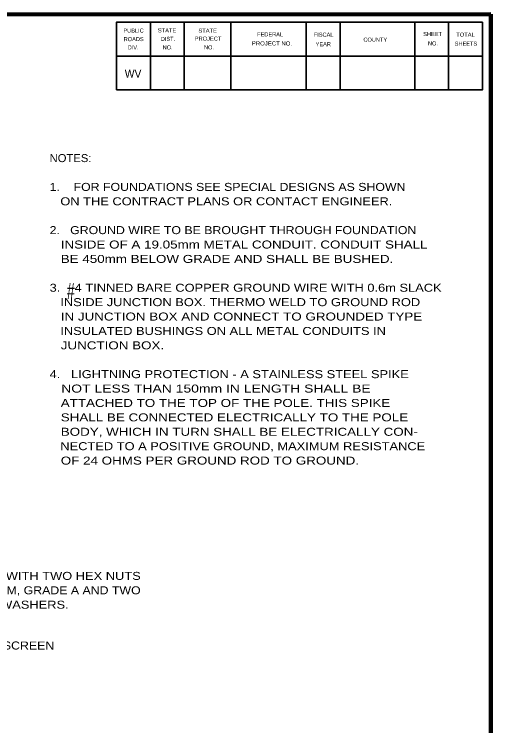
# Model space of a CAD drawing. Extents: x -24 to 689, y -7 to 446.
# Drawn here: x 534.7 to 683.4, y 218.4 to 440.6 of the extents above; entities that cross this region are included whole.
import ezdxf
from ezdxf.enums import TextEntityAlignment as Align

# ---------------------------------------------------------------- set-up
doc = ezdxf.new("R2010")
doc.units = 0
doc.layers.add('1', color=7, linetype='Continuous', lineweight=35)
doc.layers.add('61', color=7, linetype='Continuous', lineweight=35)

msp = doc.modelspace()

# ---------------------------------------------------------------- linework, layer by layer
at = {"layer": '1', "lineweight": 158}
msp.add_line((683.413, 2.23), (683.413, 440.647), dxfattribs=at)
at = {"layer": '1', "lineweight": 13}
msp.add_line((683.413, 2.23), (683.413, 440.647), dxfattribs=at)
at = {"layer": '1', "lineweight": 158}
msp.add_lwpolyline([(683.413, 440.647), (23.663, 440.564), (23.747, 2.23)], dxfattribs=at)
at = {"layer": '61'}
for p, q in [((577.163, 438.147), (577.163, 416.98)), ((587.747, 438.147), (587.747, 416.98)), ((602.247, 438.147), (602.247, 416.98)), ((625.83, 438.147), (625.83, 416.98)), ((636.413, 438.147), (636.413, 416.98)), ((659.663, 438.147), (659.663, 416.98)), ((670.247, 438.147), (670.247, 416.98)), ((680.83, 427.564), (566.58, 427.564))]:
    msp.add_line(p, q, dxfattribs=at)
for points in [[(680.83, 438.147), (566.58, 438.147), (566.58, 416.98)], [(680.83, 438.147), (680.83, 416.98), (566.58, 416.98)]]:
    msp.add_lwpolyline(points, dxfattribs=at)

# ---------------------------------------------------------------- texts
at = {"layer": '1'}
for s, height, width, p in [('WV', 2.54, 0.95, (569.163, 420.814)), ('NOTES:', 2.5, 1.05, (545.702, 394.452)), ('1.    FOR FOUNDATIONS SEE SPECIAL DESIGNS AS SHOWN', 2.5, 1.15, (545.702, 385.452)), ('   ON THE CONTRACT PLANS OR CONTACT ENGINEER.', 2.5, 1.2, (545.702, 380.952)), ('2.   GROUND WIRE TO BE BROUGHT THROUGH FOUNDATION', 2.5, 1.15, (545.702, 371.952)), ('   INSIDE OF A 19.05mm METAL CONDUIT. CONDUIT SHALL', 2.5, 1.25, (545.702, 367.452)), ('   BE 450mm BELOW GRADE AND SHALL BE BUSHED.', 2.5, 1.25, (545.702, 362.952)), ('3.    4 TINNED BARE COPPER GROUND WIRE WITH 0.6m SLACK', 2.5, 1.2, (545.702, 353.952)), ('   INSIDE JUNCTION BOX. THERMO WELD TO GROUND ROD', 2.5, 1.2, (545.702, 349.452)), ('   IN JUNCTION BOX AND CONNECT TO GROUNDED TYPE', 2.5, 1.25, (545.702, 344.952)), ('   INSULATED BUSHINGS ON ALL METAL CONDUITS IN', 2.5, 1.2, (545.702, 340.452)), ('   JUNCTION BOX.', 2.5, 1.25, (545.702, 335.952)), ('4.   LIGHTNING PROTECTION - A STAINLESS STEEL SPIKE', 2.5, 1.2, (545.702, 326.952)), ('   NOT LESS THAN 150mm IN LENGTH SHALL BE', 2.5, 1.3, (545.702, 322.452)), ('   ATTACHED TO THE TOP OF THE POLE. THIS SPIKE', 2.5, 1.25, (545.702, 317.952)), ('   SHALL BE CONNECTED ELECTRICALLY TO THE POLE', 2.5, 1.25, (545.702, 313.452)), ('   BODY, WHICH IN TURN SHALL BE ELECTRICALLY CON-', 2.5, 1.25, (545.702, 308.952)), ('   NECTED TO A POSITIVE GROUND, MAXIMUM RESISTANCE', 2.5, 1.2, (545.702, 304.452)), ('   OF 24 OHMS PER GROUND ROD TO GROUND.', 2.5, 1.25, (545.702, 299.952)), ('EACH BOLT PROVIDED WITH TWO HEX NUTS', 2.5, 1.2, (486.114, 263.93)), ('MEETING AASHTO M291/M, GRADE A AND TWO', 2.5, 1.15, (486.114, 259.43)), ('AASHTO M243/M FLAT WASHERS.', 2.5, 1.2, (486.114, 254.93))]:
    msp.add_text(s, height=height, dxfattribs=dict(at, width=width)).set_placement(p)
for s, height, width, p in [('#', 5, 0.65, (552.302, 351.66)), ('INSTALL VARMINT SCREEN', 2.5, 1.15, (521.609, 242.181))]:
    msp.add_text(s, height=height, dxfattribs=dict(at, width=width)).set_placement(p, align=Align.CENTER)
at = {"layer": '61'}
for s, height, rotation, p in [('PUBLIC', 1.271, 0.033, (568.747, 434.897)), ('ROADS', 1.27, 0.124, (568.83, 432.23)), ('DIST.', 1.27, 0.056, (580.413, 432.314)), ('FEDERAL', 1.27, 0.007, (610.497, 433.73)), ('FISCAL', 1.271, 359.942, (628.163, 433.647)), ('SHEET', 1.271, 0.059, (662.33, 433.814)), ('YEAR', 1.27, 0.105, (628.747, 430.647)), ('COUNTY', 1.269, 0.069, (643.663, 432.064)), ('SHEETS', 1.269, 359.959, (672.163, 430.814)), ('DIV.', 1.27, 359.932, (570.08, 429.647))]:
    msp.add_text(s, height=height, rotation=rotation, dxfattribs=at).set_placement(p)
for s, height, rotation, width, p in [('STATE', 1.271, 0.059, 1.05, (579.497, 434.98)), ('STATE', 1.271, 0.059, 1.05, (592.163, 434.897)), ('PROJECT', 1.27, 359.908, 1.05, (590.997, 432.397)), ('TOTAL', 1.27, 359.926, 1.05, (672.663, 433.647)), ('PROJECT NO.', 1.27, 359.922, 1.1, (608.83, 430.897)), ('NO.', 1.27, 359.852, 0.9, (663.83, 430.897)), ('NO.', 1.27, 359.852, 0.9, (580.997, 429.647)), ('NO.', 1.271, 0.225, 0.9, (593.913, 429.647))]:
    msp.add_text(s, height=height, rotation=rotation, dxfattribs=dict(at, width=width)).set_placement(p)

doc.saveas('drawing.dxf')
